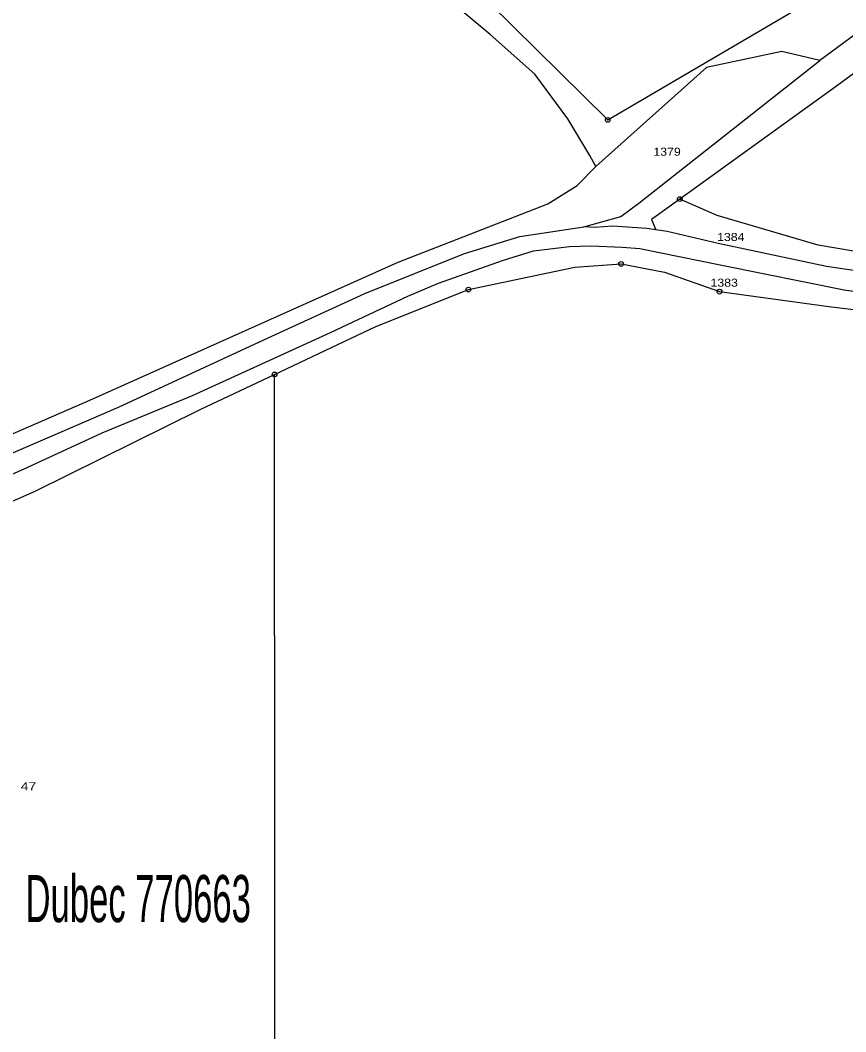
# Model space of a CAD drawing. Extents: x -872229 to -869198, y -1075981 to -1074329.
# Drawn here: x -870664.3 to -870489.1, y -1075151.2 to -1074936.4 of the extents above; entities that cross this region are included whole.
import ezdxf
from ezdxf.enums import TextEntityAlignment as Align

# ---------------------------------------------------------------- set-up
doc = ezdxf.new("R2010")
doc.units = 0
doc.header["$LTSCALE"] = 0.68
for name, color, linetype, lineweight in [('1', 7, 'Continuous', 25), ('7', 7, 'Continuous', 13), ('8', 7, 'Continuous', 25)]:
    doc.layers.add(name, color=color, linetype=linetype, lineweight=lineweight)
doc.layers.add('2', color=7, linetype='Continuous')

msp = doc.modelspace()

# ---------------------------------------------------------------- linework, layer by layer
at = {"layer": '1'}
for points in [[(-870352.08, -1074839.16), (-870370.51, -1074852.86), (-870398.03, -1074874.22), (-870412.45, -1074885.65), (-870420.69, -1074894.67), (-870447.23, -1074917.28), (-870451.03, -1074920.77), (-870491.11, -1074950.4), (-870524.35, -1074974.36)], [(-870605.12, -1074892.84), (-870539.63, -1074957.56), (-870491.54, -1074929.27), (-870432.98, -1074889.01), (-870388.3, -1074858.96)], [(-870388.3, -1074858.96), (-870401.56, -1074868.78), (-870415.98, -1074880.21), (-870424.22, -1074889.23), (-870450.76, -1074911.84), (-870454.56, -1074915.33), (-870494.64, -1074944.96)], [(-870542.19, -1074967.42), (-870543.47, -1074965.12), (-870548.12, -1074957.33), (-870555.12, -1074947.81), (-870564.62, -1074939.42), (-870592.11, -1074916.44), (-870602.17, -1074909.34), (-870607.46, -1074906.7), (-870613.94, -1074902.37)], [(-870494.64, -1074944.96), (-870502.7, -1074943), (-870518.69, -1074946.39), (-870542.19, -1074967.42)], [(-870544.73, -1074980.25), (-870536.82, -1074978.04), (-870533, -1074975.21), (-870494.64, -1074944.96)], [(-870723.96, -1075050), (-870693.71, -1075036.28), (-870649.55, -1075017.06), (-870584.14, -1074987.8), (-870552.32, -1074975.37), (-870546.15, -1074971.5), (-870542.19, -1074967.42)], [(-870524.35, -1074974.36), (-870530.38, -1074978.71), (-870529.43, -1074980.92)], [(-870115.36, -1074981.96), (-870117.37, -1074995.15), (-870140.21, -1074996.52), (-870172.56, -1075001.14), (-870203.84, -1075002.96), (-870227.79, -1075005.61), (-870254.49, -1075003.89), (-870314.81, -1075000.31), (-870361.75, -1074998.26), (-870391.78, -1074996.03), (-870411.2, -1074993.72), (-870422.25, -1074993.21), (-870453.27, -1074990.57), (-870470.34, -1074988.35), (-870494.98, -1074984.19), (-870516.43, -1074977.89), (-870524.35, -1074974.36)], [(-870760.55, -1075074.8), (-870736.8, -1075061.65), (-870716.28, -1075051.57), (-870684.01, -1075036.04), (-870643.52, -1075018.55), (-870612.61, -1075004.24), (-870591.23, -1074994.43), (-870570.04, -1074985.9), (-870558.3, -1074982.28), (-870544.73, -1074980.25)], [(-870529.43, -1074980.92), (-870531.32, -1074980.63), (-870538.56, -1074980.13), (-870542.37, -1074980.4), (-870544.73, -1074980.25)], [(-870471.11, -1074991.94), (-870493.23, -1074988.69), (-870516.16, -1074983.81), (-870527.05, -1074981.27), (-870529.43, -1074980.92)], [(-870746.19, -1075071.27), (-870732.98, -1075064.74), (-870715.15, -1075055.28), (-870702.93, -1075049.25), (-870662.75, -1075031.31), (-870646.95, -1075024.02), (-870627.8, -1075016.08), (-870598.46, -1075002.7), (-870582.08, -1074994.97), (-870575.53, -1074992.25), (-870561.97, -1074987.44), (-870555.39, -1074985.35), (-870547.72, -1074984.42), (-870543.16, -1074984.27), (-870536.54, -1074984.58), (-870532.83, -1074984.88), (-870528.68, -1074985.73), (-870515.43, -1074988.43), (-870489.43, -1074993.61), (-870451.62, -1074998.98)], [(-870610.36, -1075011.6), (-870588.87, -1075001.44), (-870569.21, -1074993.58), (-870546.64, -1074988.8), (-870536.79, -1074988.15), (-870527.6, -1074989.88), (-870515.91, -1074994.03), (-870492.69, -1074997.19), (-870452.83, -1075001.97), (-870413.18, -1075005.54), (-870363.54, -1075007.87), (-870304.97, -1075011.83), (-870245.64, -1075015.91), (-870217.62, -1075016.65), (-870207.57, -1075016.13)], [(-870746.19, -1075071.27), (-870740.01, -1075073.65), (-870701.56, -1075054.27), (-870661.14, -1075036.37), (-870626.13, -1075019.06), (-870610.36, -1075011.6)], [(-870610.3, -1075233.15), (-870610.33, -1075122.57), (-870610.36, -1075011.6)]]:
    msp.add_lwpolyline(points, dxfattribs=at)
at = {"layer": '8'}
for centre, radius in [((-870539.63, -1074957.5599), 0.5), ((-870539.63, -1074957.5599), 0.0303), ((-870524.35, -1074974.3599), 0.5), ((-870524.35, -1074974.3599), 0.0303), ((-870536.79, -1074988.1499), 0.5), ((-870536.79, -1074988.1499), 0.0303), ((-870569.21, -1074993.5799), 0.5), ((-870569.21, -1074993.5799), 0.0303), ((-870515.91, -1074994.0299), 0.5), ((-870515.91, -1074994.0299), 0.0303), ((-870610.36, -1075011.5999), 0.5), ((-870610.36, -1075011.5999), 0.0303)]:
    msp.add_circle(centre, radius, dxfattribs=at)

# ---------------------------------------------------------------- texts
at = {"layer": '2', "width": 1.15}
for s, p in [('1379', (-870529.95, -1074965.16)), ('1384', (-870516.42, -1074983.27)), ('1383', (-870517.82, -1074992.97))]:
    msp.add_text(s, height=1.7, dxfattribs=at).set_placement(p)
at = {"layer": '2', "width": 1.3}
msp.add_text('47', height=1.7, dxfattribs=at).set_placement((-870662.59, -1075099.91), align=Align.CENTER)
at = {"layer": '7', "width": 0.55}
msp.add_text('Dubec 770663', height=10, dxfattribs=at).set_placement((-870639.3, -1075127.927), align=Align.CENTER)

doc.saveas('drawing.dxf')
